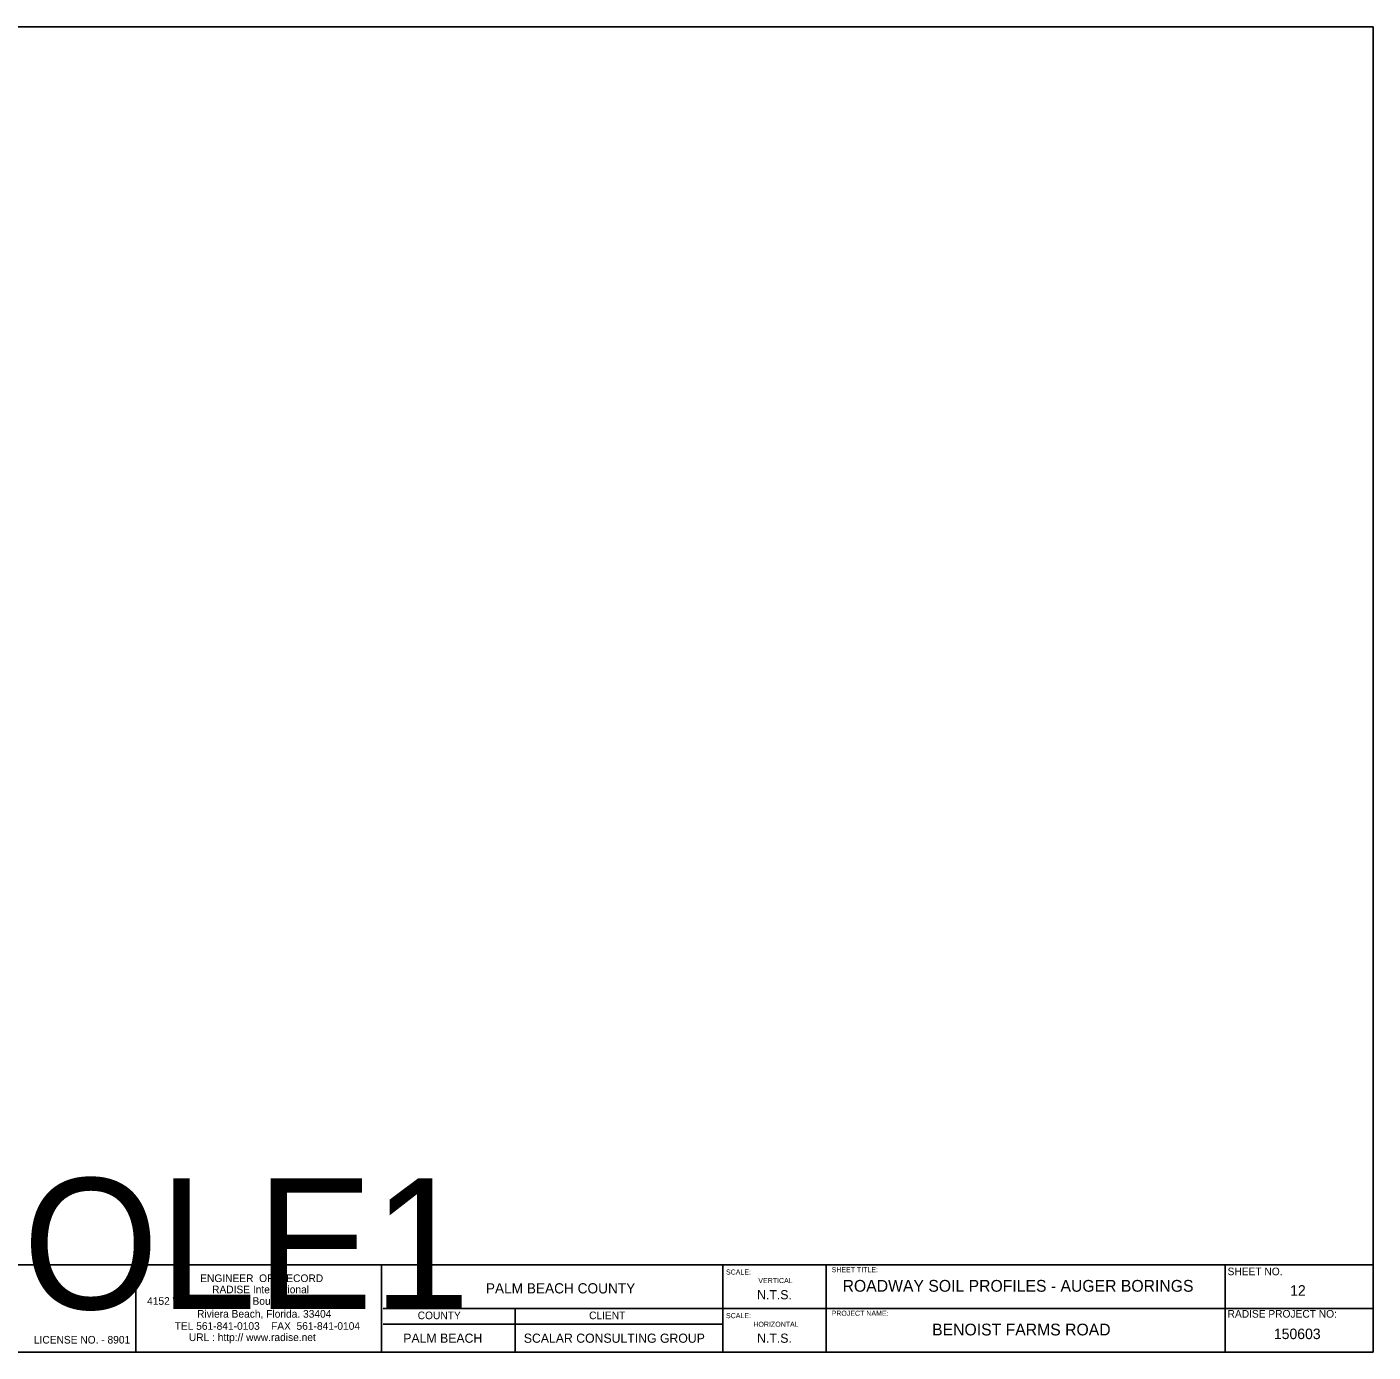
# Model space of a CAD drawing. Extents: x 0.6 to 16.4, y 0.2 to 10.3.
# Drawn here: x 6.16 to 16.45, y 0.16 to 10.29 of the extents above; entities that cross this region are included whole.
import ezdxf

# ---------------------------------------------------------------- set-up
doc = ezdxf.new("R2010")
doc.units = 0
for name, color, linetype in [('Level 1', 7, 'Continuous'), ('Level 23', 7, 'Continuous'), ('Level 24', 7, 'Continuous'), ('Level 46', 7, 'Continuous'), ('Level 63', 7, 'Continuous')]:
    doc.layers.add(name, color=color, linetype=linetype)

msp = doc.modelspace()

# ---------------------------------------------------------------- linework, layer by layer
at = {"layer": 'Level 23'}
for p, q in [((16.447, 0.161), (16.447, 10.287)), ((6.992, 0.161), (6.992, 0.827)), ((6.992, 0.161), (6.992, 0.827)), ((8.869, 0.161), (8.869, 0.827)), ((8.869, 0.161), (8.869, 0.827)), ((11.478, 0.161), (11.478, 0.827)), ((11.478, 0.161), (11.478, 0.827)), ((11.478, 0.161), (11.478, 0.827)), ((11.478, 0.161), (11.478, 0.827)), ((11.478, 0.161), (11.478, 0.827)), ((12.268, 0.161), (12.268, 0.827)), ((12.268, 0.161), (12.268, 0.827)), ((15.317, 0.161), (15.317, 0.827)), ((15.317, 0.161), (15.317, 0.827)), ((8.883, 0.494), (11.478, 0.494)), ((8.883, 0.494), (11.478, 0.494)), ((9.89, 0.494), (9.89, 0.161)), ((11.478, 0.494), (15.317, 0.494)), ((11.478, 0.494), (15.317, 0.494)), ((15.317, 0.494), (16.447, 0.494)), ((15.317, 0.494), (16.447, 0.494)), ((8.883, 0.373), (11.478, 0.373)), ((8.883, 0.373), (11.478, 0.373)), ((0.575, 0.161), (16.447, 0.161))]:
    msp.add_line(p, q, dxfattribs=at)
at = {"layer": 'Level 46'}
msp.add_line((0.573, 0.827), (16.447, 0.827), dxfattribs=at)
msp.add_line((0.573, 0.827), (16.447, 0.827), dxfattribs=at)
at = {"layer": 'Level 63'}
msp.add_lwpolyline([(0.575, 0.161), (16.447, 0.161), (16.447, 10.287), (0.575, 10.287), (0.575, 0.161)], dxfattribs=at)

# ---------------------------------------------------------------- texts
at = {"layer": 'Level 1'}
msp.add_text('OLE1', height=1, dxfattribs=at).set_placement((6.128, 0.489))
at = {"layer": 'Level 23'}
for s, height, p in [('ENGINEER  OF  RECORD', 0.05827, (7.484, 0.696)), ('SCALE:', 0.0389, (11.502, 0.753)), ('SCALE:', 0.0389, (11.502, 0.753)), ('SCALE:', 0.0389, (11.502, 0.753)), ('SCALE:', 0.0389, (11.502, 0.753)), ('SHEET TITLE:', 0.03887, (12.309, 0.771)), ('SHEET NO.', 0.0583, (15.335, 0.748)), ('RADISE International', 0.05827, (7.575, 0.61)), ('4152 West Blue Heron Boulevard, Suite 1114', 0.05827, (7.078, 0.522)), ('Riviera Beach, Florida. 33404', 0.05827, (7.46, 0.424)), ('COUNTY', 0.0583, (9.146, 0.412)), ('CLIENT', 0.0583, (10.456, 0.412)), ('SCALE:', 0.0389, (11.502, 0.42)), ('SCALE:', 0.0389, (11.502, 0.42)), ('SCALE:', 0.0389, (11.502, 0.42)), ('SCALE:', 0.0389, (11.502, 0.42)), ('PROJECT NAME:', 0.03887, (12.309, 0.438)), ('RADISE PROJECT NO:', 0.05827, (15.335, 0.424)), ('TEL 561-841-0103    FAX  561-841-0104', 0.05827, (7.289, 0.331)), ('LICENSE NO. - 8901', 0.05827, (6.213, 0.226)), ('                                                                URL : http:// www.radise.net', 0.05827, (6.012, 0.245))]:
    msp.add_text(s, height=height, dxfattribs=at).set_placement(p)
at = {"layer": 'Level 24'}
for s, height, p in [('VERTICAL', 0.0389, (11.749, 0.688)), ('PALM BEACH COUNTY ', 0.078, (9.667, 0.609)), ('N.T.S.', 0.07, (11.74, 0.564)), ('ROADWAY SOIL PROFILES - AUGER BORINGS', 0.09, (12.393, 0.622)), ('12', 0.08, (15.813, 0.592)), ('HORIZONTAL', 0.0389, (11.711, 0.354)), ('BENOIST FARMS ROAD', 0.09, (13.077, 0.288)), ('150603', 0.08, (15.689, 0.26)), ('PALM BEACH', 0.07, (9.036, 0.232)), ('SCALAR CONSULTING GROUP', 0.07, (9.957, 0.232)), ('N.T.S.', 0.07, (11.74, 0.232))]:
    msp.add_text(s, height=height, dxfattribs=at).set_placement(p)

doc.saveas('drawing.dxf')
